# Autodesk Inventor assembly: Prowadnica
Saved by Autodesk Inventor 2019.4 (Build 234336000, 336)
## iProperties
Created: 2020-01
Part Number: Prowadnica
Document SubType Name: Assembly
Designer: Administrator
Title: Prowadnica v6
Author: Administrator
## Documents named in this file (2)
- c:\worker\convert-fusion-r01\tmp\job-1\133\output\files\da311742-6a18-4413-9c1a-65dbd131a173\Prowadnica v6.iam
- c:\worker\convert-fusion-r01\tmp\job-1\133\output\files\da311742-6a18-4413-9c1a-65dbd131a173\Prowadnica v6.ipt
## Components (1 placed, 1 different names)
1. Prowadnica v6
